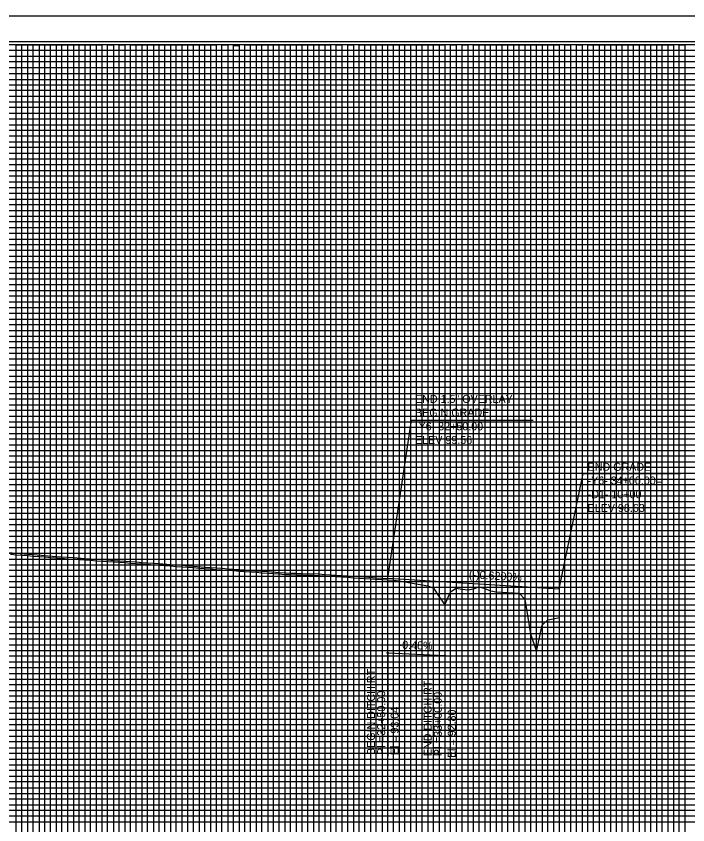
# Model space of a CAD drawing. Extents: x 2345490 to 2436403, y 465165 to 573888.
# Drawn here: x 2383692 to 2384279, y 549355 to 550063 of the extents above; entities that cross this region are included whole.
import ezdxf

# ---------------------------------------------------------------- set-up
doc = ezdxf.new("R2010")
doc.units = 0
for name, color, linetype in [('Old_Level_1', 7, 'Continuous'), ('Old_Level_18', 7, 'Continuous'), ('Old_Level_2', 7, 'Continuous'), ('Old_Level_3', 7, 'Continuous'), ('Old_Level_41', 7, 'Continuous'), ('Old_Level_42', 7, 'Continuous'), ('Old_Level_43', 7, 'Continuous'), ('Old_Level_50', 7, 'Continuous'), ('Old_Level_51', 7, 'Continuous')]:
    doc.layers.add(name, color=color, linetype=linetype)

msp = doc.modelspace()

# ---------------------------------------------------------------- linework, layer by layer
at = {"layer": 'Old_Level_1'}
for points in [[(2383686.79895, 549591.98175), (2383691.79895, 549591.58575), (2383696.79895, 549591.18975), (2383701.79895, 549590.79375), (2383706.79895, 549590.39675), (2383711.79895, 549590.00075), (2383716.79895, 549589.60475), (2383721.79895, 549589.20875), (2383726.79895, 549588.81275), (2383731.79895, 549588.42), (2383736.79895, 549588.07725), (2383741.79895, 549587.73425), (2383746.79895, 549587.39125), (2383751.79895, 549587.0485), (2383756.79895, 549586.7055), (2383761.79895, 549586.36375), (2383766.79895, 549586.02075)], [(2383766.79895, 549586.02075), (2383771.79895, 549585.678), (2383776.79895, 549585.335), (2383781.79895, 549584.99225), (2383786.79895, 549584.64925), (2383791.79895, 549584.3075), (2383796.79895, 549583.96475), (2383801.79895, 549583.61275), (2383806.79895, 549583.23925), (2383811.79895, 549582.86575), (2383816.79895, 549582.4925), (2383821.79895, 549582.119), (2383826.79895, 549581.7455), (2383831.79895, 549581.367), (2383836.79895, 549580.9935), (2383841.79895, 549580.62025), (2383846.79895, 549580.24675), (2383851.79895, 549579.87325), (2383856.79895, 549579.5), (2383861.79895, 549579.12175), (2383866.79895, 549578.74825), (2383871.79895, 549578.3815), (2383876.79895, 549578.01625), (2383881.79895, 549577.651), (2383886.79895, 549577.28575), (2383891.79895, 549576.92025), (2383896.79895, 549576.55425), (2383901.79895, 549576.2015), (2383906.79895, 549575.83675), (2383911.79895, 549575.47225), (2383916.79895, 549575.1075), (2383921.79895, 549574.74275), (2383926.79895, 549574.3835), (2383931.79895, 549574.19925), (2383936.79895, 549574.0435), (2383941.79895, 549573.888), (2383946.79895, 549573.73225), (2383951.79895, 549573.5765), (2383956.79895, 549573.42075), (2383961.79895, 549573.10725), (2383966.79895, 549572.78025), (2383971.79895, 549572.45325), (2383976.79895, 549572.126), (2383981.79895, 549571.799), (2383986.79895, 549571.46825), (2383991.79895, 549571.1395), (2383996.79895, 549570.8125), (2384001.79895, 549570.4855), (2384006.79895, 549570.15825), (2384011.79895, 549569.83125), (2384016.79895, 549569.50075), (2384021.79895, 549569.172), (2384026.79895, 549568.78475), (2384031.79895, 549567.93775), (2384036.79895, 549567.03925), (2384041.79895, 549566.14075), (2384046.79895, 549565.24225), (2384051.79895, 549564.34375), (2384056.79895, 549562.38025), (2384061.79895, 549554.77175), (2384066.79895, 549547.6085), (2384071.79895, 549559.20475), (2384076.79895, 549562.23675), (2384081.79895, 549561.5745), (2384086.79895, 549560.9125), (2384091.79895, 549561.6495), (2384096.79895, 549563.46225), (2384101.79895, 549562.0125), (2384106.79895, 549560.106), (2384111.79895, 549559.0465), (2384116.79895, 549558.81775), (2384121.79895, 549558.589), (2384126.79895, 549558.33075), (2384131.79895, 549557.903), (2384136.79895, 549552.799), (2384141.79895, 549522.467), (2384146.79895, 549506.94325), (2384151.79895, 549529.902), (2384156.79895, 549534.74625), (2384161.79895, 549535.40025), (2384166.79895, 549536.7405)]]:
    msp.add_lwpolyline(points, dxfattribs=at)
at = {"layer": 'Old_Level_18'}
msp.add_lwpolyline([(2384616.79875, 550037.754), (2383116.79875, 550037.754), (2383116.79875, 548987.754), (2384616.79875, 548987.754)], close=True, dxfattribs=at)
at = {"layer": 'Old_Level_2'}
for p, q in [((2384016.799, 549570.9665), (2384037.61165, 549709.27237)), ((2384037.61165, 549709.27237), (2384143.87439, 549709.27237)), ((2384166.799, 549561.6665), (2384187.61165, 549662.53587)), ((2384187.61165, 549662.53587), (2384272.87566, 549662.53587)), ((2384016.799, 549570.9665), (2384166.799, 549561.6665))]:
    msp.add_line(p, q, dxfattribs=at)
for points in [[(2383681.90159, 549593.67369), (2383701.90172, 549592.08968), (2383706.90172, 549591.69268), (2383726.90117, 549590.10873), (2383731.89431, 549589.71651), (2383736.88789, 549589.3742), (2383741.8879, 549589.0312), (2383751.8879, 549588.34545), (2383756.88776, 549588.00246), (2383761.88776, 549587.66071), (2383766.88792, 549587.3177)], [(2383766.88786, 549587.31771), (2383771.88789, 549586.97495), (2383776.88789, 549586.63195), (2383781.88789, 549586.2892), (2383786.88776, 549585.94621), (2383791.88773, 549585.60447), (2383796.88905, 549585.26162), (2383801.89302, 549584.90935), (2383806.89577, 549584.53564), (2383816.89577, 549583.78889), (2383826.89643, 549583.04184), (2383831.89643, 549582.66334), (2383836.89576, 549582.28989), (2383841.89576, 549581.91664), (2383846.89577, 549581.54314), (2383856.89639, 549580.79634), (2383861.8964, 549580.41809), (2383866.89492, 549580.0447), (2383871.89386, 549579.67803), (2383876.89367, 549579.31279), (2383891.89377, 549578.21679), (2383896.89215, 549577.85091), (2383901.89199, 549577.49817), (2383906.8935, 549577.13331), (2383911.8935, 549576.76881), (2383921.89282, 549576.03936), (2383926.86949, 549575.68178), (2383931.84312, 549575.4985), (2383936.83939, 549575.34287), (2383941.83939, 549575.18737), (2383956.85988, 549574.71948), (2383961.88204, 549574.40459), (2383966.8838, 549574.07748), (2383976.8838, 549573.42323), (2383981.88427, 549573.0962), (2383986.8845, 549572.76543), (2383991.88401, 549572.43671), (2383996.8838, 549572.10973), (2384006.8838, 549571.45548), (2384011.88424, 549571.12845), (2384016.78828, 549570.80429)]]:
    msp.add_lwpolyline(points, dxfattribs=at)
at = {"layer": 'Old_Level_3'}
for p, q in [((2384016.79875, 549505.7665), (2384016.79875, 549415.21593)), ((2384016.79875, 549505.7665), (2384066.79875, 549503.3665)), ((2384066.79875, 549503.3665), (2384066.79875, 549414.02887))]:
    msp.add_line(p, q, dxfattribs=at)
for centre in [(2384016.79875, 549505.7665), (2384066.79875, 549503.3665)]:
    msp.add_circle(centre, 0.5, dxfattribs=at)
at = {"layer": 'Old_Level_41'}
for points in [[(2383691.79875, 549012.754), (2383691.79875, 550037.754), (2383741.79875, 550037.754), (2383741.79875, 549012.754)], [(2383716.79875, 549012.754), (2383716.79875, 550037.754), (2383766.79875, 550037.754), (2383766.79875, 549012.754)], [(2383791.79875, 549012.754), (2383791.79875, 550037.754), (2383841.79875, 550037.754), (2383841.79875, 549012.754)], [(2383816.79875, 549012.754), (2383816.79875, 550037.754), (2383866.79875, 550037.754), (2383866.79875, 549012.754)], [(2383891.79875, 549012.754), (2383891.79875, 550037.754), (2383941.79875, 550037.754), (2383941.79875, 549012.754)], [(2383916.79875, 549012.754), (2383916.79875, 550037.754), (2383966.79875, 550037.754), (2383966.79875, 549012.754)], [(2383991.79875, 549012.754), (2383991.79875, 550037.754), (2384041.79875, 550037.754), (2384041.79875, 549012.754)], [(2384016.79875, 549012.754), (2384016.79875, 550037.754), (2384066.79875, 550037.754), (2384066.79875, 549012.754)], [(2384091.79875, 549012.754), (2384091.79875, 550037.754), (2384141.79875, 550037.754), (2384141.79875, 549012.754)], [(2384116.79875, 549012.754), (2384116.79875, 550037.754), (2384166.79875, 550037.754), (2384166.79875, 549012.754)], [(2384191.79875, 549012.754), (2384191.79875, 550037.754), (2384241.79875, 550037.754), (2384241.79875, 549012.754)], [(2384216.79875, 549012.754), (2384216.79875, 550037.754), (2384266.79875, 550037.754), (2384266.79875, 549012.754)], [(2383116.79875, 549987.754), (2384416.74875, 549987.754)], [(2384416.74875, 549937.754), (2383116.79875, 549937.754), (2383116.79875, 549887.704), (2384616.79875, 549887.704)], [(2384616.79875, 549862.754), (2383116.79875, 549862.754), (2383116.79875, 549912.754), (2384416.74875, 549912.754)], [(2384616.79875, 549837.754), (2383116.79875, 549837.754), (2383116.79875, 549787.754), (2384616.79875, 549787.754)], [(2384616.79875, 549762.754), (2383116.79875, 549762.754), (2383116.79875, 549812.754), (2384616.79875, 549812.754)], [(2384616.79875, 549737.754), (2383116.79875, 549737.754), (2383116.79875, 549687.754), (2384616.79875, 549687.754)], [(2384616.79875, 549637.754), (2383116.79875, 549637.754), (2383116.79875, 549587.754), (2384616.79875, 549587.754)], [(2384616.79875, 549537.754), (2383116.79875, 549537.754), (2383116.79875, 549487.754), (2384616.79875, 549487.754)], [(2384616.79875, 549437.754), (2383116.79875, 549437.754), (2383116.79875, 549387.754), (2384616.79875, 549387.754)], [(2384616.79875, 549362.754), (2383116.79875, 549362.754), (2383116.79875, 549412.754), (2384616.79875, 549412.754)]]:
    msp.add_lwpolyline(points, dxfattribs=at)
at = {"layer": 'Old_Level_42'}
for points in [[(2384416.74875, 549962.754), (2383116.89875, 549962.754), (2383116.89875, 550012.704), (2384416.74875, 550012.704)], [(2384616.79875, 549662.754), (2383116.79875, 549662.754), (2383116.79875, 549712.754), (2384616.79875, 549712.754)], [(2384616.79875, 549562.754), (2383116.79875, 549562.754), (2383116.79875, 549612.754), (2384616.79875, 549612.754)], [(2384616.79875, 549462.754), (2383116.79875, 549462.754), (2383116.79875, 549512.754), (2384616.79875, 549512.754)]]:
    msp.add_lwpolyline(points, dxfattribs=at)
at = {"layer": 'Old_Level_43'}
for p, q in [((2384566.79875, 549857.754), (2383166.79875, 549857.754)), ((2383166.79875, 549852.754), (2384566.79875, 549852.754)), ((2384566.79875, 549832.754), (2383166.79875, 549832.754))]:
    msp.add_line(p, q, dxfattribs=at)
for points in [[(2384416.74875, 550032.754), (2383166.79875, 550032.754), (2383166.79875, 550027.754), (2384416.74875, 550027.754)], [(2383696.79875, 549012.754), (2383696.79875, 550037.754), (2383701.79875, 550037.754), (2383701.79875, 549012.754)], [(2383706.79875, 549012.754), (2383706.79875, 550037.754), (2383711.79875, 550037.754), (2383711.79875, 549012.754)], [(2383721.79875, 549012.754), (2383721.79875, 550037.754), (2383726.79875, 550037.754), (2383726.79875, 549012.754)], [(2383731.79875, 549012.754), (2383731.79875, 550037.754), (2383736.79875, 550037.754), (2383736.79875, 549012.754)], [(2383746.79875, 549012.754), (2383746.79875, 550037.754), (2383751.79875, 550037.754), (2383751.79875, 549012.754)], [(2383756.79875, 549012.754), (2383756.79875, 550037.754), (2383761.79875, 550037.754), (2383761.79875, 549012.754)], [(2383771.79875, 549012.754), (2383771.79875, 550037.754), (2383776.79875, 550037.754), (2383776.79875, 549012.754)], [(2383781.79875, 549012.754), (2383781.79875, 550037.754), (2383786.79875, 550037.754), (2383786.79875, 549012.754)], [(2383796.79875, 549012.754), (2383796.79875, 550037.754), (2383801.79875, 550037.754), (2383801.79875, 549012.754)], [(2383806.79875, 549012.754), (2383806.79875, 550037.754), (2383811.79875, 550037.754), (2383811.79875, 549012.754)], [(2383821.79875, 549012.754), (2383821.79875, 550037.754), (2383826.79875, 550037.754), (2383826.79875, 549012.754)], [(2383831.79875, 549012.754), (2383831.79875, 550037.754), (2383836.79875, 550037.754), (2383836.79875, 549012.754)], [(2383846.79875, 549012.754), (2383846.79875, 550037.754), (2383851.79875, 550037.754), (2383851.79875, 549012.754)], [(2383856.79875, 549012.754), (2383856.79875, 550037.754), (2383861.79875, 550037.754), (2383861.79875, 549012.754)], [(2383871.79875, 549012.754), (2383871.79875, 550037.754), (2383876.79875, 550037.754), (2383876.79875, 549012.754)], [(2383881.79875, 549012.754), (2383881.79875, 550037.154), (2383886.79875, 550037.154), (2383886.79875, 549012.754)], [(2383896.79875, 549012.754), (2383896.79875, 550037.754), (2383901.79875, 550037.754), (2383901.79875, 549012.754)], [(2383906.79875, 549012.754), (2383906.79875, 550037.754), (2383911.79875, 550037.754), (2383911.79875, 549012.754)], [(2383921.79875, 549012.754), (2383921.79875, 550037.754), (2383926.79875, 550037.754), (2383926.79875, 549012.754)], [(2383931.79875, 549012.754), (2383931.79875, 550037.754), (2383936.79875, 550037.754), (2383936.79875, 549012.754)], [(2383946.79875, 549012.754), (2383946.79875, 550037.754), (2383951.79875, 550037.754), (2383951.79875, 549012.754)], [(2383956.79875, 549012.754), (2383956.79875, 550037.754), (2383961.79875, 550037.754), (2383961.79875, 549012.754)], [(2383971.79875, 549012.754), (2383971.79875, 550037.754), (2383976.79875, 550037.754), (2383976.79875, 549012.754)], [(2383981.79875, 549012.754), (2383981.79875, 550037.754), (2383986.79875, 550037.754), (2383986.79875, 549012.754)], [(2383996.79875, 549012.754), (2383996.79875, 550037.754), (2384001.79875, 550037.754), (2384001.79875, 549012.754)], [(2384006.79875, 549012.754), (2384006.79875, 550037.754), (2384011.79875, 550037.754), (2384011.79875, 549012.754)], [(2384021.79875, 549012.754), (2384021.79875, 550037.754), (2384026.79875, 550037.754), (2384026.79875, 549012.754)], [(2384031.79875, 549012.754), (2384031.79875, 550037.754), (2384036.79875, 550037.754), (2384036.79875, 549012.754)], [(2384046.79875, 549012.754), (2384046.79875, 550037.754), (2384051.79875, 550037.754), (2384051.79875, 549012.754)], [(2384056.79875, 549012.754), (2384056.79875, 550037.754), (2384061.79875, 550037.754), (2384061.79875, 549012.754)], [(2384071.79875, 549012.754), (2384071.79875, 550037.754), (2384076.79875, 550037.754), (2384076.79875, 549012.754)], [(2384081.79875, 549012.754), (2384081.79875, 550037.754), (2384086.79875, 550037.754), (2384086.79875, 549012.754)], [(2384096.79875, 549012.754), (2384096.79875, 550037.754), (2384101.79875, 550037.754), (2384101.79875, 549012.754)], [(2384106.79875, 549012.754), (2384106.79875, 550037.754), (2384111.79875, 550037.754), (2384111.79875, 549012.754)], [(2384121.79875, 549012.754), (2384121.79875, 550037.754), (2384126.79875, 550037.754), (2384126.79875, 549012.754)], [(2384131.79875, 549012.754), (2384131.79875, 550037.754), (2384136.79875, 550037.754), (2384136.79875, 549012.754)], [(2384146.79875, 549012.754), (2384146.79875, 550037.754), (2384151.79875, 550037.754), (2384151.79875, 549012.754)], [(2384156.79875, 549012.754), (2384156.79875, 550037.754), (2384161.79875, 550037.754), (2384161.79875, 549012.754)], [(2384171.79875, 549012.754), (2384171.79875, 550037.754), (2384176.79875, 550037.754), (2384176.79875, 549012.754)], [(2384181.79875, 549012.754), (2384181.79875, 550037.754), (2384186.79875, 550037.754), (2384186.79875, 549012.754)], [(2384196.79875, 549012.754), (2384196.79875, 550037.754), (2384201.79875, 550037.754), (2384201.79875, 549012.754)], [(2384206.79875, 549012.754), (2384206.79875, 550037.754), (2384211.79875, 550037.754), (2384211.79875, 549012.754)], [(2384221.79875, 549012.754), (2384221.79875, 550037.754), (2384226.79875, 550037.754), (2384226.79875, 549012.754)], [(2384231.79875, 549012.754), (2384231.79875, 550037.754), (2384236.79875, 550037.754), (2384236.79875, 549012.754)], [(2384246.79875, 549012.754), (2384246.79875, 550037.754), (2384251.79875, 550037.754), (2384251.79875, 549012.754)], [(2384256.79875, 549012.754), (2384256.79875, 550037.754), (2384261.79875, 550037.754), (2384261.79875, 549012.754)], [(2384271.79875, 549012.754), (2384271.79875, 550037.754), (2384276.79875, 550037.754), (2384276.79875, 549012.754)], [(2384416.74875, 550022.754), (2383166.79875, 550022.754), (2383166.79875, 550017.754), (2384416.74875, 550017.754)], [(2384416.74875, 550007.004), (2383167.79875, 550007.004), (2383167.79875, 550002.754), (2384416.74875, 550002.754)], [(2384416.74875, 549997.754), (2383166.79875, 549997.754), (2383166.79875, 549992.754), (2384416.74875, 549992.754)], [(2384416.74875, 549982.754), (2383166.79875, 549982.754), (2383166.79875, 549977.754), (2384416.74875, 549977.754)], [(2384416.74875, 549972.754), (2383166.79875, 549972.754), (2383166.79875, 549967.754), (2384416.74875, 549967.754)], [(2384416.74875, 549957.754), (2383166.79875, 549957.754), (2383166.79875, 549952.754), (2384416.74875, 549952.754)], [(2384416.74875, 549947.754), (2383166.79875, 549947.754), (2383166.79875, 549942.754), (2384416.74875, 549942.754)], [(2384416.74875, 549932.754), (2383166.79875, 549932.754), (2383166.79875, 549927.754), (2384416.74875, 549927.754)], [(2384416.74875, 549922.754), (2383166.79875, 549922.754), (2383166.79875, 549917.754), (2384416.74875, 549917.754)], [(2384416.74875, 549907.754), (2383166.79875, 549907.754), (2383166.79875, 549902.754), (2384416.74875, 549902.754)], [(2384566.79875, 549897.754), (2383166.79875, 549897.754), (2383166.79875, 549897.754), (2383166.79875, 549877.754), (2384566.79875, 549877.754)], [(2383166.79875, 549892.754), (2384566.79875, 549892.754)], [(2384566.79875, 549882.754), (2383166.79875, 549882.754)], [(2384566.79875, 549872.754), (2383166.79875, 549872.754), (2383166.79875, 549867.754), (2384566.79875, 549867.754)], [(2384566.79875, 549847.754), (2383166.79875, 549847.754), (2383166.79875, 549842.754), (2384566.79875, 549842.754)], [(2384566.79875, 549827.754), (2383166.79875, 549827.754), (2383166.79875, 549822.754), (2384566.79875, 549822.754)], [(2384566.79875, 549817.754), (2383166.79875, 549817.754)], [(2383166.79875, 549807.754), (2384566.79875, 549807.754)], [(2384566.79875, 549802.754), (2383166.79875, 549802.754), (2383166.79875, 549797.754), (2384566.79875, 549797.754)], [(2384566.79875, 549792.754), (2383166.79875, 549792.754), (2383166.79875, 549782.754), (2384566.79875, 549782.754)], [(2384566.79875, 549777.754), (2383166.79875, 549777.754), (2383166.79875, 549772.754), (2384566.79875, 549772.754)], [(2384566.79875, 549767.754), (2383166.79875, 549767.754), (2383166.79875, 549757.754), (2384566.79875, 549757.754)], [(2384566.79875, 549752.754), (2383166.79875, 549752.754), (2383166.79875, 549747.754), (2384566.79875, 549747.754)], [(2384566.79875, 549742.754), (2383166.79875, 549742.754), (2383166.79875, 549732.754), (2384566.79875, 549732.754)], [(2384566.79875, 549727.754), (2383166.79875, 549727.754), (2383166.79875, 549722.754), (2384566.79875, 549722.754)], [(2384566.79875, 549717.754), (2383166.79875, 549717.754), (2383166.79875, 549707.754), (2384566.79875, 549707.754)], [(2384566.79875, 549702.754), (2383166.79875, 549702.754), (2383166.79875, 549697.754), (2384566.79875, 549697.754)], [(2384566.79875, 549692.754), (2383166.79875, 549692.754), (2383166.79875, 549682.754), (2384566.79875, 549682.754)], [(2384566.79875, 549677.754), (2383166.79875, 549677.754), (2383166.79875, 549672.754), (2384566.79875, 549672.754)], [(2384566.79875, 549667.754), (2383166.79875, 549667.754), (2383166.79875, 549657.754), (2384566.79875, 549657.754)], [(2384566.79875, 549652.754), (2383166.79875, 549652.754), (2383166.79875, 549647.754), (2384566.79875, 549647.754)], [(2384566.79875, 549642.754), (2383166.79875, 549642.754), (2383166.79875, 549632.754), (2384566.79875, 549632.754)], [(2384566.79875, 549627.754), (2383166.79875, 549627.754), (2383166.79875, 549622.754), (2384566.79875, 549622.754)], [(2384566.79875, 549617.754), (2383166.79875, 549617.754), (2383166.79875, 549607.754), (2384566.79875, 549607.754)], [(2384566.79875, 549602.754), (2383166.79875, 549602.754), (2383166.79875, 549597.754), (2384566.79875, 549597.754)], [(2384566.79875, 549592.754), (2383166.79875, 549592.754), (2383166.79875, 549582.754), (2384566.79875, 549582.754)], [(2384566.79875, 549577.754), (2383166.79875, 549577.754), (2383166.79875, 549572.754), (2384566.79875, 549572.754)], [(2384566.79875, 549567.754), (2383166.79875, 549567.754), (2383166.79875, 549557.754), (2384566.79875, 549557.754)], [(2384566.79875, 549552.754), (2383166.79875, 549552.754), (2383166.79875, 549547.754), (2384566.79875, 549547.754)], [(2384566.79875, 549542.754), (2383166.79875, 549542.754), (2383166.79875, 549532.754), (2384566.79875, 549532.754)], [(2384566.79875, 549527.754), (2383166.79875, 549527.754), (2383166.79875, 549522.754), (2384566.79875, 549522.754)], [(2384566.79875, 549517.754), (2383166.79875, 549517.754)], [(2383166.79875, 549507.754), (2384566.79875, 549507.754)], [(2384566.79875, 549502.754), (2383166.79875, 549502.754), (2383166.79875, 549497.754), (2384566.79875, 549497.754)], [(2384566.79875, 549492.754), (2383166.79875, 549492.754), (2383166.79875, 549482.754), (2384566.79875, 549482.754)], [(2384566.79875, 549477.754), (2383166.79875, 549477.754), (2383166.79875, 549472.754), (2384566.79875, 549472.754)], [(2384566.79875, 549467.754), (2383166.79875, 549467.754), (2383166.79875, 549457.754), (2384566.79875, 549457.754)], [(2384566.79875, 549452.754), (2383166.79875, 549452.754), (2383166.79875, 549447.754), (2384566.79875, 549447.754)], [(2384566.79875, 549442.754), (2383166.79875, 549442.754), (2383166.79875, 549432.754), (2384566.79875, 549432.754)], [(2384566.79875, 549427.754), (2383166.79875, 549427.754), (2383166.79875, 549422.754), (2384566.79875, 549422.754)], [(2384566.79875, 549417.754), (2383166.79875, 549417.754), (2383166.79875, 549407.754), (2384566.79875, 549407.754)], [(2384566.79875, 549402.754), (2383166.79875, 549402.754), (2383166.79875, 549397.754), (2384566.79875, 549397.754)], [(2384566.79875, 549392.754), (2383166.79875, 549392.754), (2383166.79875, 549382.754), (2384566.79875, 549382.754)], [(2384566.79875, 549377.754), (2383166.79875, 549377.754), (2383166.79875, 549372.754), (2384566.79875, 549372.754)], [(2384566.79875, 549367.754), (2383166.79875, 549367.754), (2383166.79875, 549357.754), (2384566.79875, 549357.754)]]:
    msp.add_lwpolyline(points, dxfattribs=at)
at = {"layer": 'Old_Level_50'}
msp.add_lwpolyline([(2384629.29875, 550040.304), (2382962.79875, 550040.304), (2382962.79875, 548985.204), (2384629.29875, 548985.204)], close=True, dxfattribs=at)
at = {"layer": 'Old_Level_51'}
msp.add_lwpolyline([(2384633.79875, 550062.754), (2382949.79875, 550062.754), (2382949.79875, 548962.754), (2384633.79875, 548962.754)], close=True, dxfattribs=at)

# ---------------------------------------------------------------- texts
at = {"layer": 'Old_Level_2'}
for s, height, p in [('END 1.5" OVERLAY', 7.0000005, (2384040.6625, 549724.42846)), ('BEGIN GRADE', 7.0000005, (2384040.6625, 549712.42821)), ('-Y6- 32+50.00', 7.0000005, (2384040.6625, 549700.42821)), ('ELEV 99.56', 7.000001, (2384040.6625, 549688.42821)), ('END GRADE', 7.000001, (2384191.62925, 549664.99363)), ('-Y6- 34+00.00=', 7.0000005, (2384191.62925, 549652.99338)), ('-D1- 10+00', 7.000001, (2384191.62925, 549640.99338)), ('ELEV 98.63', 7.000001, (2384191.62925, 549628.99338))]:
    msp.add_text(s, height=height, dxfattribs=at).set_placement(p)
msp.add_text('(-)0.6200%', height=7.000001, rotation=356.45220278, dxfattribs=at).set_placement((2384087.63472, 549571.08325))
at = {"layer": 'Old_Level_3'}
for s, height, rotation, p in [('-0.48%', 7, 358.00148517, (2384026.27475, 549509.35519)), ('BEGIN DITCH RT', 7.0000005, 90, (2384005.68744, 549416.33602)), ('END DITCH RT', 7.0000005, 90, (2384055.21261, 549415.36049)), ('PI =32+50.00', 7.0000005, 90, (2384014.56134, 549416.33602)), ('PI =33+00.00', 7.0000005, 90, (2384064.08651, 549415.36049)), ('El = 93.04', 7.000001, 90, (2384026.27357, 549416.0986)), ('El = 92.80', 7.000001, 90, (2384076.27357, 549413.6986))]:
    msp.add_text(s, height=height, rotation=rotation, dxfattribs=at).set_placement(p)

doc.saveas('drawing.dxf')
